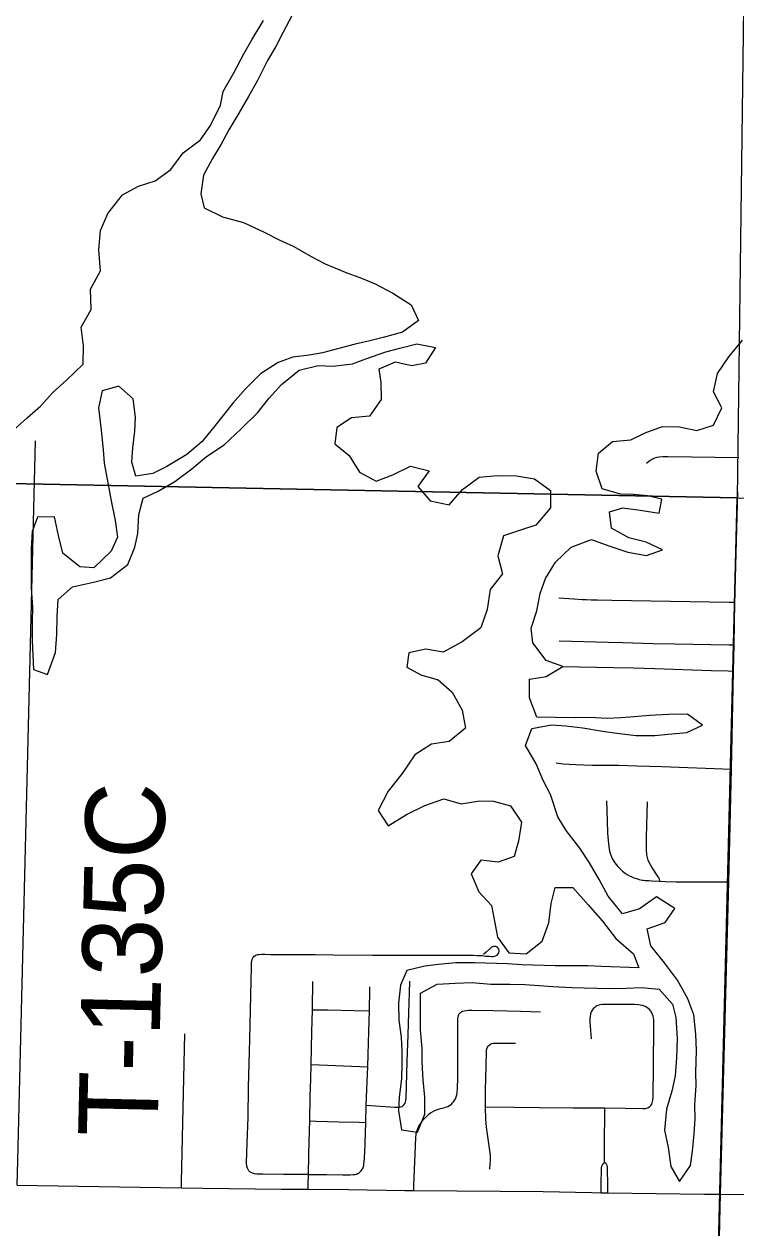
# Model space of a CAD drawing. Extents: x -38.1 to 35.9, y -2.7 to 28.5.
# Drawn here: x 23.615 to 24.124, y 17.464 to 18.326 of the extents above; entities that cross this region are included whole.
import ezdxf

# ---------------------------------------------------------------- set-up
doc = ezdxf.new("R2010")
doc.units = 0
for name, color, linetype in [('GM_X_Interchange_Ramps', 7, 'Continuous'), ('GM_X_Interstate_Shield', 7, 'Continuous'), ('GM_X_Major_River_Text', 7, 'Continuous'), ('GM_X_Minor_Lake', 7, 'Continuous'), ('GM_X_US_Route', 7, 'Continuous')]:
    doc.layers.add(name, color=color, linetype=linetype)

msp = doc.modelspace()

# ---------------------------------------------------------------- linework, layer by layer
at = {"layer": 'GM_X_Interchange_Ramps'}
msp.add_lwpolyline([(23.60987, 17.49479), (23.69774, 17.49333), (23.72744, 17.49292), (23.74247, 17.49271), (23.79902, 17.4921), (23.81792, 17.49196), (23.84687, 17.49174), (23.88726, 17.49108), (23.89352, 17.49103), (23.98605, 17.49027), (24.02085, 17.48958), (24.0275, 17.48949), (24.03247, 17.48943), (24.10163, 17.48848), (24.11302, 17.48833), (24.18437, 17.48741), (24.27496, 17.48562), (24.31037, 17.48475), (24.40417, 17.48244), (24.48182, 17.48095), (24.52284, 17.48016), (24.61517, 17.47824)], dxfattribs=at)
at = {"layer": 'GM_X_Interstate_Shield'}
for points in [[(23.80668, 18.33203), (23.80023, 18.3197), (23.795, 18.30961), (23.789, 18.29954), (23.78174, 18.28533), (23.77532, 18.27375), (23.76851, 18.26181), (23.76132, 18.24988), (23.75571, 18.23979), (23.7497, 18.22935), (23.74327, 18.21739), (23.74136, 18.20416), (23.74372, 18.19423), (23.75682, 18.18777), (23.77189, 18.18353), (23.7865, 18.17666), (23.79773, 18.17101), (23.80785, 18.16654), (23.82017, 18.15935), (23.83027, 18.15412), (23.84452, 18.14801), (23.85618, 18.14388), (23.86593, 18.13979), (23.87864, 18.13297), (23.89169, 18.12462), (23.89706, 18.11346), (23.88541, 18.10507), (23.87163, 18.1013), (23.86206, 18.09892), (23.85174, 18.09657), (23.8391, 18.09314), (23.82839, 18.09042), (23.81884, 18.08881), (23.80702, 18.08725), (23.79665, 18.08338), (23.78388, 18.07541), (23.77331, 18.06471), (23.76426, 18.05435), (23.75243, 18.03952), (23.74218, 18.02692), (23.73127, 18.01775), (23.71696, 18.00906), (23.70694, 18.00404), (23.69473, 18.00212), (23.69198, 18.01207), (23.69267, 18.0223), (23.69416, 18.0344), (23.69446, 18.04426), (23.69295, 18.05758), (23.68258, 18.06661), (23.67071, 18.06317), (23.66807, 18.0511), (23.66988, 18.03511), (23.67136, 18.02102), (23.67222, 18.01151), (23.67484, 17.99739), (23.67711, 17.98442), (23.68011, 17.9703), (23.68166, 17.95849), (23.67718, 17.94837), (23.66468, 17.93659), (23.65482, 17.93726), (23.64258, 17.94711), (23.63954, 17.95972), (23.63651, 17.97309), (23.62435, 17.97269)], [(23.74812, 18.25292), (23.75539, 18.26751), (23.7572, 18.27732), (23.76481, 18.29076), (23.77205, 18.30421), (23.77766, 18.31429), (23.78605, 18.32809)], [(23.6033, 18.03136), (23.61696, 18.04387), (23.6267, 18.05231), (23.63535, 18.06192), (23.6451, 18.07075), (23.65722, 18.08216), (23.65723, 18.09544), (23.65573, 18.10876), (23.66294, 18.12146), (23.66223, 18.1359), (23.66945, 18.14897), (23.66838, 18.16418), (23.66955, 18.1778), (23.67485, 18.19017), (23.68512, 18.20353), (23.6967, 18.20965), (23.70858, 18.21347), (23.71984, 18.22149), (23.72855, 18.23338), (23.74098, 18.24288), (23.74812, 18.25292)], [(23.78981, 18.05778), (23.79885, 18.06776), (23.81169, 18.07801), (23.82508, 18.08141), (23.83569, 18.08072), (23.8498, 18.08258), (23.8594, 18.0861), (23.8736, 18.09099), (23.88356, 18.09374), (23.8958, 18.09679), (23.90902, 18.09413), (23.90185, 18.08296), (23.8923, 18.08096), (23.88022, 18.08359), (23.86868, 18.07861), (23.86991, 18.06909), (23.87031, 18.05694), (23.86198, 18.04504), (23.84904, 18.0439), (23.83858, 18.03699), (23.83709, 18.02528), (23.84748, 18.017), (23.85472, 18.00503), (23.86669, 17.9986), (23.8786, 18.00319), (23.89131, 18.00926), (23.9045, 18.00584), (23.89658, 17.99469), (23.90539, 17.98456), (23.91898, 17.98151), (23.92842, 17.99262), (23.94045, 18.00137), (23.9534, 18.00251), (23.96708, 18.00249), (23.97992, 18.00021), (23.99145, 17.9919), (23.99146, 17.97938), (23.98084, 17.96717), (23.97125, 17.96404), (23.95783, 17.9595), (23.9536, 17.9452), (23.95702, 17.9322), (23.94833, 17.92107), (23.94601, 17.90672), (23.94144, 17.89357), (23.92823, 17.88371), (23.91471, 17.87614), (23.90225, 17.8784), (23.89001, 17.87572), (23.88857, 17.86552), (23.89866, 17.85991), (23.91109, 17.85651), (23.92108, 17.84749), (23.9283, 17.83475), (23.93058, 17.82178), (23.9189, 17.81226), (23.90631, 17.81035), (23.89431, 17.80274), (23.88517, 17.78934), (23.8753, 17.77673), (23.86806, 17.7629), (23.87533, 17.75206), (23.88848, 17.76002), (23.90159, 17.76647), (23.91503, 17.77139), (23.92745, 17.76761), (23.94081, 17.76987), (23.95068, 17.76958), (23.96273, 17.76619), (23.97074, 17.75457), (23.96844, 17.74098), (23.96546, 17.73006), (23.95394, 17.72585), (23.94145, 17.72735), (23.93471, 17.71768), (23.94002, 17.70463), (23.94922, 17.69487), (23.95152, 17.68266), (23.95349, 17.67235), (23.96152, 17.66111), (23.97403, 17.66036), (23.98532, 17.66952), (23.99026, 17.68266), (23.9918, 17.69628), (23.99481, 17.70795), (24.00734, 17.70796), (24.01837, 17.69549), (24.02866, 17.68381), (24.03817, 17.67138), (24.05075, 17.66039), (24.05464, 17.65041), (24.02769, 17.6512), (24.01822, 17.65186), (24.00758, 17.65179), (23.99467, 17.65179), (23.97076, 17.65249), (23.96052, 17.65317), (23.93699, 17.65386), (23.9237, 17.65387), (23.91113, 17.65272), (23.9016, 17.65148)], [(23.98822, 17.87018), (23.97873, 17.88299), (23.97751, 17.89327), (23.98168, 17.90567), (23.98395, 17.91813), (23.98769, 17.92902), (23.99487, 17.94057), (24.0062, 17.95125), (24.0208, 17.95689), (24.0332, 17.95235), (24.04674, 17.94778), (24.05996, 17.94549), (24.07147, 17.94933), (24.05987, 17.95498), (24.04742, 17.95801), (24.03509, 17.96482), (24.03354, 17.97663), (24.04312, 17.97938), (24.05561, 17.97788), (24.06921, 17.97558), (24.07103, 17.98578), (24.06084, 17.98797), (24.051, 17.98902), (24.04151, 17.9893), (24.02833, 17.9931), (24.02415, 18.00574), (24.02567, 18.0186), (24.03579, 18.02703), (24.04874, 18.02817), (24.05914, 18.03318), (24.07143, 18.03775), (24.08358, 18.0374), (24.09603, 18.03475), (24.10792, 18.03858), (24.11399, 18.05092), (24.10787, 18.06249), (24.11092, 18.07568), (24.11887, 18.08759), (24.12872, 18.09945)], [(23.62435, 17.97269), (23.62063, 17.96255), (23.61988, 17.95005), (23.61983, 17.93563), (23.61982, 17.92235), (23.62092, 17.90828), (23.62062, 17.89804), (23.62059, 17.88438), (23.6215, 17.86386), (23.63165, 17.86015), (23.63743, 17.87592), (23.63819, 17.8888), (23.63858, 17.90169), (23.63931, 17.91381), (23.64946, 17.923), (23.66438, 17.92636), (23.67662, 17.92942), (23.68906, 17.93892), (23.69398, 17.95129), (23.69617, 17.9611), (23.69695, 17.97474), (23.69996, 17.98641), (23.71074, 17.99141), (23.72272, 17.99827), (23.73476, 18.0074), (23.74528, 18.0162), (23.75806, 18.02456), (23.77018, 18.03596), (23.78191, 18.04738), (23.78981, 18.05778)], [(23.9016, 17.65148), (23.88859, 17.64845), (23.88411, 17.63796), (23.88258, 17.6251), (23.88298, 17.61294), (23.88452, 17.60076), (23.88499, 17.59088), (23.88509, 17.58138), (23.88479, 17.57115), (23.88324, 17.55753), (23.88258, 17.54806), (23.88483, 17.53434), (23.89618, 17.53287), (23.9015, 17.54561), (23.90148, 17.55775), (23.90033, 17.57031), (23.89957, 17.58286), (23.89948, 17.59273), (23.89835, 17.60604), (23.89837, 17.61932), (23.89837, 17.63223), (23.91033, 17.63871), (23.92327, 17.63946), (23.93544, 17.63987), (23.9487, 17.63872), (23.96237, 17.6387), (23.973, 17.63838), (23.98323, 17.63771), (23.99309, 17.63703), (24.00674, 17.63626), (24.0333, 17.63548), (24.04547, 17.63588), (24.05612, 17.63632), (24.069, 17.63519), (24.07855, 17.62428), (24.08093, 17.61472), (24.08201, 17.59989), (24.08159, 17.58586), (24.08045, 17.57299), (24.07823, 17.56205), (24.07443, 17.54926), (24.07284, 17.53413), (24.07552, 17.52191), (24.07739, 17.50819), (24.08353, 17.49738), (24.09146, 17.50892), (24.09291, 17.51912), (24.09404, 17.53161), (24.09473, 17.54221), (24.09465, 17.55246), (24.09544, 17.5661), (24.09534, 17.57559), (24.0958, 17.59114), (24.09539, 17.60292), (24.0939, 17.61662), (24.08968, 17.62813), (24.0821, 17.64163), (24.07298, 17.65404), (24.06308, 17.6661), (24.0604, 17.67832), (24.07345, 17.68287), (24.08021, 17.69292), (24.06716, 17.70127), (24.05512, 17.69252), (24.04287, 17.68908), (24.0326, 17.70153), (24.02612, 17.71348), (24.01926, 17.72545), (24.01235, 17.7359), (24.00248, 17.74871), (23.99668, 17.75837), (23.99146, 17.77446), (23.98606, 17.78448), (23.9811, 17.79639), (23.97351, 17.80952), (23.97805, 17.82153), (23.99218, 17.82415), (24.00241, 17.82347), (24.01452, 17.82198), (24.02851, 17.81967), (24.03872, 17.81823), (24.05235, 17.81669), (24.06602, 17.81667), (24.07554, 17.81753), (24.08887, 17.81866), (24.10005, 17.82402), (24.08926, 17.83192), (24.07596, 17.83156), (24.06226, 17.83082), (24.05122, 17.83001), (24.0417, 17.82915), (24.03181, 17.82868), (24.0193, 17.82943), (24.00904, 17.82935), (23.99499, 17.82938), (23.98171, 17.82977), (23.97642, 17.84359), (23.97644, 17.85687), (23.98827, 17.8588), (24.00026, 17.86604), (23.98822, 17.87018)]]:
    msp.add_lwpolyline(points, dxfattribs=at)
at = {"layer": 'GM_X_Major_River_Text'}
for p, q in [((24.1232, 17.91188), (24.12534, 17.99093)), ((24.12265, 17.88141), (24.1232, 17.91188)), ((24.12228, 17.8627), (24.12265, 17.88141)), ((24.12073, 17.79262), (24.12228, 17.8627)), ((24.11889, 17.71184), (24.12073, 17.79262)), ((24.11302, 17.48833), (24.11889, 17.71184)), ((23.82008, 17.58109), (23.8606, 17.5795))]:
    msp.add_line(p, q, dxfattribs=at)
for points in [[(23.60987, 17.49479), (23.61031, 17.51242), (23.62298, 18.02747)], [(24.06005, 18.01151), (24.06175, 18.01294), (24.06319, 18.01393), (24.06456, 18.01465), (24.06604, 18.01521), (24.06759, 18.01563), (24.06914, 18.01588), (24.07167, 18.01609), (24.07519, 18.01615), (24.12601, 18.01552)], [(23.99725, 17.91508), (24.00814, 17.91428), (24.01412, 17.91393), (24.01693, 17.91382), (24.02049, 17.91373), (24.02508, 17.91364), (24.03518, 17.91351), (24.1191, 17.91192), (24.1232, 17.91188)], [(23.99747, 17.88441), (24.03257, 17.88333), (24.04312, 17.88304), (24.06475, 17.88247), (24.08009, 17.88216), (24.1192, 17.88147), (24.12265, 17.88141)], [(23.99964, 17.86605), (24.03673, 17.86534), (24.05082, 17.86497), (24.05812, 17.86476), (24.0659, 17.86452), (24.10624, 17.86315), (24.11848, 17.86281), (24.12228, 17.8627)], [(23.99543, 17.79696), (24.00037, 17.79643), (24.00472, 17.79608), (24.00941, 17.79578), (24.01517, 17.79561), (24.02141, 17.79548), (24.02779, 17.79543), (24.03997, 17.79525), (24.0531, 17.79499), (24.0622, 17.79471), (24.07102, 17.79438), (24.12073, 17.79262)], [(24.03137, 17.76989), (24.03183, 17.75576), (24.03221, 17.74667), (24.03255, 17.74142), (24.03299, 17.73721), (24.03357, 17.7338), (24.03422, 17.73171), (24.03491, 17.72987), (24.03575, 17.72806), (24.03737, 17.72551), (24.03928, 17.72306), (24.04135, 17.72092), (24.04294, 17.71953), (24.04474, 17.71819), (24.04617, 17.71725), (24.04797, 17.71623), (24.04955, 17.71545), (24.05109, 17.71482), (24.05283, 17.71422), (24.05473, 17.71367), (24.057, 17.71319), (24.05777, 17.71307), (24.05907, 17.71292), (24.05987, 17.71285), (24.06178, 17.71274), (24.06388, 17.71262), (24.06882, 17.71233), (24.06953, 17.7123), (24.07339, 17.71212), (24.081, 17.71197), (24.11889, 17.71184)], [(24.06953, 17.7123), (24.06957, 17.71296), (24.06943, 17.71372), (24.0684, 17.71545), (24.06381, 17.7224), (24.06278, 17.72411), (24.06197, 17.72572), (24.0613, 17.72734), (24.06074, 17.72932), (24.06038, 17.73128), (24.06002, 17.7351), (24.06005, 17.74375), (24.06065, 17.76904)], [(23.81818, 17.50257), (23.80039, 17.50261), (23.78562, 17.50264), (23.78267, 17.50272), (23.78124, 17.50284), (23.77961, 17.50306), (23.77811, 17.50352), (23.77716, 17.50396), (23.77639, 17.50451), (23.77568, 17.50516), (23.77506, 17.50602), (23.77462, 17.50693), (23.77425, 17.50832), (23.77399, 17.51089), (23.77444, 17.5251), (23.77501, 17.54326), (23.77546, 17.56502), (23.77626, 17.5992), (23.77701, 17.63088), (23.77743, 17.6509), (23.77751, 17.65274), (23.77756, 17.65364), (23.77762, 17.65446), (23.77771, 17.65512), (23.778, 17.65636), (23.77825, 17.65709), (23.77857, 17.65763), (23.77915, 17.65837), (23.78003, 17.65908), (23.78092, 17.65955), (23.78176, 17.6598), (23.78307, 17.65997), (23.78465, 17.66006), (23.78693, 17.66009), (23.79081, 17.66002), (23.81194, 17.65992), (23.8231, 17.65979), (23.83612, 17.65965), (23.86407, 17.65943), (23.88643, 17.65933), (23.91871, 17.65938), (23.9255, 17.65935), (23.93594, 17.65938), (23.93883, 17.6593), (23.94271, 17.65908), (23.94498, 17.65882), (23.94743, 17.6586), (23.94951, 17.6585), (23.95028, 17.65853), (23.95125, 17.65864), (23.9521, 17.65886), (23.95321, 17.65948), (23.95404, 17.66036), (23.95443, 17.66118), (23.95462, 17.66206), (23.95458, 17.66288), (23.95438, 17.66367), (23.95392, 17.66442), (23.95335, 17.66498), (23.95278, 17.66535), (23.9521, 17.6656), (23.95135, 17.6657), (23.95064, 17.66565), (23.94991, 17.66544), (23.94895, 17.66493), (23.94836, 17.6645), (23.9479, 17.66407), (23.94533, 17.66152), (23.94347, 17.65982)], [(23.81792, 17.49196), (23.81801, 17.49563), (23.81818, 17.50257), (23.81852, 17.51656), (23.81875, 17.5259), (23.81911, 17.54083), (23.81954, 17.55838), (23.81984, 17.57105), (23.82008, 17.58109), (23.82036, 17.59262), (23.82065, 17.60464), (23.82104, 17.62042), (23.82118, 17.62692), (23.82136, 17.63531), (23.82147, 17.6407)], [(23.85955, 17.55212), (23.87981, 17.55073), (23.88067, 17.55068), (23.88189, 17.55066), (23.88266, 17.5507), (23.88336, 17.55077), (23.88439, 17.551), (23.88512, 17.55126), (23.88575, 17.55164), (23.88625, 17.55207), (23.88677, 17.55268), (23.8873, 17.55358), (23.88765, 17.55452), (23.88787, 17.55539), (23.88797, 17.55609), (23.88805, 17.5569), (23.88833, 17.56561), (23.88889, 17.58325), (23.88948, 17.60231), (23.88998, 17.61806), (23.89043, 17.63239), (23.89069, 17.64076)], [(23.81818, 17.50257), (23.83116, 17.50243), (23.84284, 17.5023), (23.84814, 17.50228), (23.85023, 17.50241), (23.85163, 17.50258), (23.85255, 17.50281), (23.85387, 17.50334), (23.85449, 17.50376), (23.85502, 17.50422), (23.85567, 17.50486), (23.85639, 17.50578), (23.85706, 17.50689), (23.85779, 17.50889), (23.85797, 17.51006), (23.85817, 17.51178), (23.85831, 17.51397), (23.8584, 17.51581), (23.85848, 17.51788), (23.85917, 17.53966), (23.85955, 17.55212), (23.85997, 17.5632), (23.8602, 17.56902), (23.8606, 17.5795), (23.86087, 17.58832), (23.86136, 17.60453), (23.86181, 17.61962), (23.86191, 17.62389), (23.86207, 17.6307), (23.86215, 17.63689)], [(24.06243, 17.55112), (24.06316, 17.55191), (24.06373, 17.55275), (24.0642, 17.55378), (24.06441, 17.55465), (24.06458, 17.55574), (24.0647, 17.55795), (24.06493, 17.58033), (24.06532, 17.60874), (24.06534, 17.60993), (24.06532, 17.61158), (24.06529, 17.61227), (24.06521, 17.61329), (24.06509, 17.61424), (24.06478, 17.61575), (24.06437, 17.61707), (24.06391, 17.61813), (24.06316, 17.61932), (24.06234, 17.62031), (24.06093, 17.62151), (24.05967, 17.62238), (24.05856, 17.62295), (24.05717, 17.62346), (24.05557, 17.62376), (24.05425, 17.62393), (24.0514, 17.62409), (24.03168, 17.62417), (24.0285, 17.6241), (24.02698, 17.62392), (24.02584, 17.62363), (24.02453, 17.62309), (24.02382, 17.62265), (24.02304, 17.62204), (24.02195, 17.62096), (24.02123, 17.62007), (24.0205, 17.6189), (24.01998, 17.61745), (24.01963, 17.61553), (24.01956, 17.6143), (24.01955, 17.61273), (24.01957, 17.61115), (24.01972, 17.60861), (24.0204, 17.59945)], [(23.82104, 17.62042), (23.83202, 17.62021), (23.85094, 17.61984), (23.86181, 17.61962)], [(23.89352, 17.49103), (23.89366, 17.49476), (23.89475, 17.52288), (23.89485, 17.52505), (23.89493, 17.52673), (23.89502, 17.52834), (23.89509, 17.52929), (23.89524, 17.53079), (23.89539, 17.53184), (23.89568, 17.5331), (23.89599, 17.53413), (23.8965, 17.5355), (23.89719, 17.53697), (23.89829, 17.53884), (23.89962, 17.54073), (23.90051, 17.54179), (23.90216, 17.54355), (23.90292, 17.54429), (23.90373, 17.54506), (23.9047, 17.54586), (23.90561, 17.54656), (23.90654, 17.54716), (23.90805, 17.548), (23.90908, 17.54848), (23.91121, 17.54919), (23.91277, 17.54961), (23.91506, 17.55017), (23.91638, 17.55061), (23.91788, 17.55123), (23.9191, 17.55187), (23.92021, 17.55268), (23.92131, 17.5537), (23.92198, 17.55449), (23.92247, 17.55517), (23.9229, 17.55584), (23.92337, 17.55674), (23.9239, 17.55801), (23.92431, 17.55949), (23.92451, 17.56061), (23.92466, 17.56176), (23.92481, 17.56346), (23.92493, 17.56571), (23.92504, 17.56993), (23.92509, 17.5889), (23.92512, 17.60421), (23.92515, 17.61339), (23.92518, 17.61419), (23.92524, 17.61497), (23.9255, 17.61637), (23.92573, 17.61694), (23.92607, 17.61752), (23.92698, 17.61844), (23.92841, 17.61926), (23.92971, 17.61964), (23.93113, 17.61986), (23.93257, 17.61996), (23.93512, 17.62006), (23.95048, 17.61972), (23.96993, 17.61927), (23.98412, 17.61895)], [(23.72744, 17.49292), (23.72753, 17.49699), (23.7298, 17.60314)], [(23.948, 17.50631), (23.9483, 17.51006), (23.94843, 17.5121), (23.94849, 17.51341), (23.94839, 17.51542), (23.9482, 17.51806), (23.9457, 17.53628), (23.94541, 17.53916), (23.94516, 17.54214), (23.945, 17.54481), (23.94486, 17.54804), (23.94477, 17.55085), (23.94487, 17.56276), (23.94533, 17.57967), (23.94557, 17.59124), (23.94584, 17.59247), (23.94629, 17.59359), (23.94684, 17.59441), (23.94759, 17.59514), (23.94837, 17.59564), (23.94942, 17.59611), (23.95041, 17.59635), (23.9518, 17.59651), (23.96643, 17.59641)], [(23.94477, 17.55085), (23.96524, 17.55067), (23.98361, 17.55051), (24.0075, 17.5503), (24.03014, 17.5501), (24.04486, 17.5499), (24.05732, 17.54972), (24.05853, 17.54973), (24.05933, 17.54981), (24.06005, 17.54994), (24.06083, 17.55015), (24.06143, 17.55045), (24.06243, 17.55112)], [(24.03247, 17.48943), (24.03234, 17.49559), (24.03214, 17.50608), (24.03211, 17.50706), (24.03205, 17.50805), (24.03189, 17.50904), (24.0315, 17.50985), (24.03102, 17.51032), (24.03008, 17.51103), (24.03011, 17.52728), (24.03014, 17.54501), (24.03014, 17.5501)], [(23.81911, 17.54083), (23.82365, 17.54071), (23.8399, 17.54026), (23.85457, 17.53986), (23.85917, 17.53966)], [(24.0275, 17.48949), (24.02764, 17.49568), (24.02788, 17.50648), (24.02792, 17.50732), (24.0281, 17.50853), (24.02845, 17.50944), (24.02917, 17.51026), (24.03008, 17.51103)], [(24.09065, 16.48126), (24.09079, 16.4877), (24.093, 16.59531), (24.09407, 16.64766), (24.09612, 16.74459), (24.09734, 16.803), (24.0991, 16.88545), (24.10061, 16.97762), (24.10354, 17.10873), (24.10427, 17.1342), (24.10609, 17.20938), (24.10715, 17.25288), (24.10749, 17.2684), (24.11182, 17.43473), (24.11254, 17.46835), (24.11302, 17.48833)]]:
    msp.add_lwpolyline(points, dxfattribs=at)
at = {"layer": 'GM_X_US_Route'}
for points in [[(23.1004, 19.00392), (24.1377, 18.98286), (24.12478, 17.98667), (23.0833, 18.00706)], [(24.12478, 17.98667), (24.09987, 16.98408), (23.08302, 17.00397), (23.0833, 18.00706)], [(24.12478, 17.98667), (25.12451, 17.96419), (25.10497, 16.96445), (24.09987, 16.98408)]]:
    msp.add_lwpolyline(points, close=True, dxfattribs=at)

# ---------------------------------------------------------------- texts
at = {"layer": 'GM_X_Minor_Lake'}
msp.add_text('T-135C', height=0.056818, rotation=88.67322, dxfattribs=at).set_placement((23.71024, 17.52909))

doc.saveas('drawing.dxf')
